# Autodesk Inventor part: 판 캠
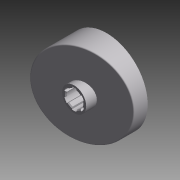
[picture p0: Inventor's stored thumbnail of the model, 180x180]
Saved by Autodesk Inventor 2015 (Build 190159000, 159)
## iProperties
Created: 2012-05
Part Number: 판 캠
Document SubType Name: 모델링
Designer: SeoGD™
Material: 강철
Appearance: 알루미늄 - 평지
Mass: 681.587 g
Surface Area: 331.303 cm^2
Volume: 86.8264 cm^3
Density: 7.85 g/cm^3
변환 표준: STEP AP214IS
파일 이름: C:\Users\SeoGD\Desktop\?쒗뿕\??stp
전처리기: Build: 253, Release: 2010 SP1 - Date: Wed 07/29/2009
전송 단위: 밀리미터
불확실성: 0.01
Author: SeoGD™
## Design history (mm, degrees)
node "작업 평면4"
sketch "스케치1"
  geometry: C1 r 44.5 at (0, 0); 1 further point
  constraints: 1 centre point, 1 coincident
  dimensions: "d25" = 89 diameter of C1
extrude "돌출1" new body sketch "스케치1" distance "d1" = 40; taper "d2" = 0 deg
sketch "스케치2"
  geometry: L1 (-44.5, 15)-(44.5, 38.847); L2 (-44.5, 0)-(-44.5, 40) reference; L3 (-44.5, 40)-(44.5, 40) reference; L4 (44.5, 0)-(44.5, 40) reference; 1 further point
  constraints: 2 end point, 2 point on line
  dimensions: "d26" = 15 distance of L2.start L1.start; "d27" = 75 deg angle of L1 L2
extrude "돌출2" cut sketch "스케치2" stored distance "d5" = 40; taper "d6" = 0 deg
node "작업 평면1"
sketch "스케치3"
  geometry: C1 r 13 at (0, 0); 1 further point
  constraints: 1 centre point, 1 coincident
  dimensions: "d9" = 26 diameter of C1
extrude "돌출3" join sketch "스케치3" distance "d10" = 38; taper "d11" = 0 deg
hole "구멍1" diameter "d14" = 18; stored, may be unused: countersink angle "d18" = 90 deg, drill point angle "d20" = 118 deg; dims "d12" = 10, "d13" = 10, "d15" = 6, "d16" = 4, "d17" = 2, "d19" = 8
feature "쉘2" dims "d29" = 5
sketch "스케치6"
  geometry: C1 r 17.5 at (0, 0); C2 r 14 at (0, 0) reference; 1 further point
  constraints: 1 centre point, 1 coincident
  dimensions: "d28" = 35 diameter of C1
extrude "돌출4" join sketch "스케치6" stored distance "d30" = 38; taper "d31" = 0 deg
fillet "모깎기1" dims "d32" = 3
chamfer "모따기1" distance "d21" = 1; stored, may be unused: second distance "d22" = 2, angle "d23" = 45 deg
sketch "스케치7"
  geometry: L1 (-12.374, 12.374)-(-27.931, 27.931); A1 r 39.5 centre (0, 0) between (-27.931, 27.931) and (0, 39.5) reference; 2 further points
  constraints: 2 end point, 2 point on circle, 1 point on line, 1 vertical alignment, 2 other
  dimensions: "d33" = 45 deg dimension on point (0, 0) L1.start A1.end
feature "리브1" sketch "스케치7" dims "d34" = 5, "d35" = 1, "d36" = 0
fillet "모깎기2" dims "d37" = 3
sketch "스케치8"
  geometry: L1 (2.5, 10.712)-(2.5, 8.646); L2 (-2.5, 10.712)-(-2.5, 8.646); A1 r 11 centre (0, 0) between (2.5, 10.712) and (-2.5, 10.712); A2 r 9 centre (0, 0) between (2.5, 8.646) and (-2.5, 8.646) reference; 1 further point
  constraints: 4 end point, 4 point on circle, 2 parallel, 1 centre point, 1 coincident, 1 vertical
  dimensions: "d41" = 22 diameter of A1; "d42" = 5 distance between parallel lines of L1 L2
extrude "돌출5" cut sketch "스케치8" stored distance "d43" = 38; taper "d44" = 0 deg
fillet "모깎기3" dims "d48" = 1
node "솔리드1"
node "솔리드 본체"
node "곡면 본체"
pattern_circular "원형 패턴1" dims angle "d39" = 360 deg
pattern_circular "원형 패턴2" dims angle "d46" = 360 deg
node "솔리드2"
